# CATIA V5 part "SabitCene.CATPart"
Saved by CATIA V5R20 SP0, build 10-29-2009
Part number: Part1.7
Bounding box of the stored display mesh (mm): x -50 to 50, y 0 to 80, z -10 to 10
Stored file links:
  C:\Users\metin\Desktop\CatiaDers\SabitCene.CATPart
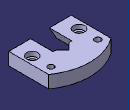
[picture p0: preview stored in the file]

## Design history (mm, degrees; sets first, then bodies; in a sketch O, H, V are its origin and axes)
Body1 (main body)
  Sketch1 on xy-plane, origin (0, 0, 0), H (1, 0, 0), V (0, 1, 0)
    point P1 (-50, 0)
    line L1 (-50, 0) -> (-50, 63.7386)
    point P2 (-50, 63.7386)
    arc A1 centre (0, -5) radius 85 from (-50, 63.7386) to (50, 63.7386) cw
    point P4 (50, 63.7386)
    point P5 (50, 0)
    line L2 (-50, 0) -> (-15, 0)
    line L3 (-15, 0) -> (-15, 36)
    line L4 (-15, 36) -> (-10, 36)
    line L5 (-10, 36) -> (0, 46)
    point P9 (0, 46)
    line L6 (0, 46) -> (10, 36)
    point P10 (10, 36)
    point P11 (10, 36)
    line L7 (10, 36) -> (15, 36)
    line L8 (15, 36) -> (15, 0)
    point P13 (15, 0)
    line L9 (15, 0) -> (50, 0)
    point P14 (50, 63.7386)
    point P15 (50, 0)
    line L10 (50, 0) -> (50, 63.7386)
    circle A2 centre (-37.5, 55) radius 5
    point P16 (-37.5, 55)
    point P17 (37.5, 55)
    circle A3 centre (37.5, 55) radius 5
    distance A1 H = 80
    length L3 = 36
    distance L8 L3 = 30
    distance P9 L7 = 10
    radius A1 = 85
    length L7 = 5
    length L4 = 5
    distance L10 L1 = 100
    radius A2 = 5
    distance P16 P17 = 75
    distance P17 H = 55
    coincidence: P1 H, P5 H, P9 V, P10 L4, P11 L6, P11 L4, P13 H, P4 P14, P5 P15, P10 P11
    vertical: L1 V, L3 V, L8 V
    horizontal: L2 H, L4 H, L7 H, L9 H
    symmetry: L8 L3 V, P2 P14 V, P1 P15 V, L1 L10 V, A2 A3 V
  Pad1: profile Sketch1, direction (0, 0, 1), length 10, mirrored extent
  Sketch2 on face of Pad1 from Sketch1.L9, origin (0, 0, 0), H (1, 0, 0), V (0, 0, 1)
    point P1 (15, -10)
    line L1 (15, -10) -> (26.547, -10)
    point P2 (26.547, -10)
    line L2 (26.547, -10) -> (15, 10)
    point P3 (15, 10)
    line L3 (15, 10) -> (15, -10)
    reference projected line E1 (15, 10) -> (50, 10) from edge [face of Pad1 from Sketch1.L9 | end face of Pad1]
    reference projected line E2 (15, -10) -> (50, -10) from edge [start face of Pad1 | face of Pad1 from Sketch1.L9]
    reference projected line E3 (15, -10) -> (15, 10) from edge [face of Pad1 from Sketch1.L9 | face of Pad1 from Sketch1.L8]
    point P4 (-15, -10)
    point P5 (-15, 10)
    line L4 (-15, 10) -> (-15, -10)
    point P6 (-26.547, -10)
    line L5 (-26.547, -10) -> (-15, 10)
    line L6 (-15, -10) -> (-26.547, -10)
    angle L2 L5 = 60
    horizontal: L1 H
    vertical: L3 V
    coincidence: P3 E1, L1 E2, L3 E3
    symmetry: P1 P4 V, P3 P5 V, L3 L4 V, P2 P6 V, L2 L5 V, L1 L6 V
  Pocket1: profile Sketch2, direction (0, 1, 0), up to face of Pad1 from Sketch1.L4
  Sketch3 on end face of Pad1, origin (33.5713, 16.8981, 10), H (1, 0, 0), V (0, 1, 0)
    point P1 (3.9287, 8.1019)
    reference intersected line E1 through (0, -16.8981) direction (-1, 0) from zx-plane
    reference intersected line E2 through (-33.5713, 0) direction (0, 1) from yz-plane
    distance P1 E1 = 25
    distance P1 E2 = 37.5
  Hole1: placed by Sketch3, at (37.5, 25, 10) direction (0, 0, -1), diameter 10.5, through (limit type 6), counterbore diameter 18, counterbore depth 7.3
  Mirror1: of Hole1, about yz-plane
